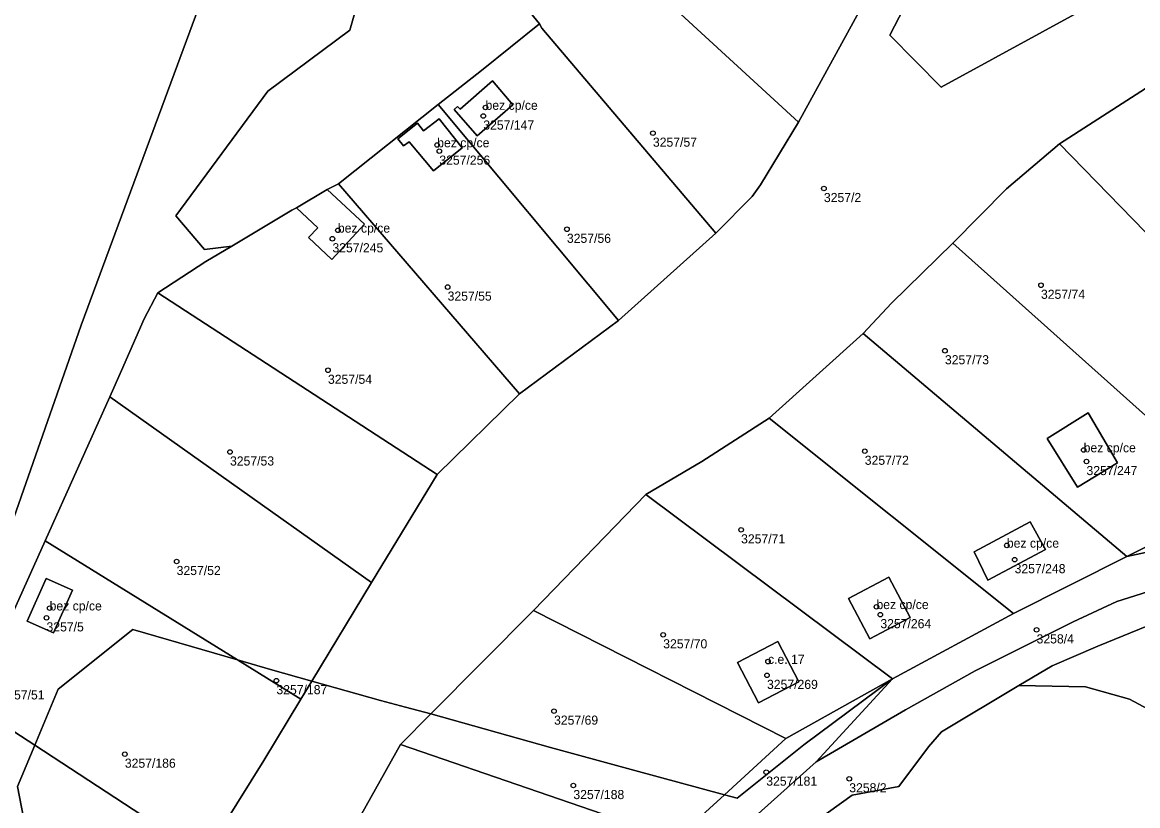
# Model space of a CAD drawing. Extents: x -878211 to -870363, y -1058464 to -1052522.
# Drawn here: x -876063.3 to -875941, y -1056644.4 to -1056558.5 of the extents above; entities that cross this region are included whole.
import ezdxf

# ---------------------------------------------------------------- set-up
doc = ezdxf.new("R2010")
doc.units = 0
for name, color, linetype in [('Definiční body', 7, 'Continuous'), ('Polygon budovy', 7, 'Continuous'), ('Polygon parcely', 7, 'Continuous')]:
    doc.layers.add(name, color=color, linetype=linetype)

msp = doc.modelspace()

# ---------------------------------------------------------------- linework, layer by layer
at = {"layer": 'Definiční body'}
for centre in [(-876012.71, -1056568.79994), (-876012.46, -1056567.86994), (-875994.11, -1056570.67994), (-876017.76, -1056571.97994), (-876017.53, -1056572.64994), (-875975.36, -1056576.74994), (-876003.54, -1056581.21994), (-876029.25, -1056582.25994), (-876028.65, -1056581.33994), (-875951.56, -1056587.35994), (-876016.62, -1056587.55994), (-875962.09, -1056594.53994), (-876029.74, -1056596.67994), (-876040.48, -1056605.63994), (-875970.88, -1056605.55994), (-875946.88, -1056605.42994), (-875946.57, -1056606.68994), (-875984.44, -1056614.17994), (-875955.3, -1056615.88994), (-876046.33, -1056617.64994), (-875954.45, -1056617.44994), (-876060.26, -1056622.76994), (-875969.6, -1056622.61994), (-876060.6, -1056623.82994), (-875969.17, -1056623.47994), (-875952.04, -1056625.14994), (-875992.98, -1056625.68994), (-875981.49, -1056628.62994), (-875981.6, -1056630.13994), (-876035.39, -1056630.71994), (-876004.95, -1056634.05994), (-876052.01, -1056638.77994), (-875981.68, -1056640.74994), (-876002.83, -1056642.21994), (-875972.58, -1056641.47994)]:
    msp.add_circle(centre, 0.25, dxfattribs=at)
at = {"layer": 'Polygon budovy'}
for points in [[(-876015.52, -1056567.76), (-876015.9, -1056568.09), (-876013.38, -1056570.98), (-876009.47, -1056567.58), (-876011.69, -1056564.96), (-876015.26, -1056568.06)], [(-876022.07, -1056571.29), (-876021.45, -1056572.06), (-876020.84, -1056571.63), (-876018.17, -1056574.83), (-876015.03, -1056572.28), (-876017.54, -1056569.11), (-876019.27, -1056570.43), (-876019.93, -1056569.59)], [(-876033.2, -1056578.86), (-876030.85, -1056581.06), (-876031.87, -1056582.14), (-876029.33, -1056584.52), (-876025.75, -1056580.65), (-876028.29, -1056578.3), (-876029.84, -1056576.87)], [(-875946.39, -1056601.36), (-875950.88, -1056604.15), (-875947.56, -1056609.49), (-875943.18, -1056606.83)], [(-875952.75, -1056613.31), (-875958.9, -1056616.58), (-875957.37, -1056619.69), (-875951.05, -1056616.32)], [(-876060.64, -1056619.51), (-876062.72, -1056624.18), (-876059.83, -1056625.47), (-876057.75, -1056620.8)], [(-875970.34, -1056626.14), (-875965.91, -1056623.8), (-875968.23, -1056619.37), (-875972.67, -1056621.7)], [(-875980.42, -1056626.43), (-875984.84, -1056628.74), (-875982.53, -1056633.16), (-875978.12, -1056630.85)]]:
    msp.add_lwpolyline(points, close=True, dxfattribs=at)
at = {"layer": 'Polygon parcely'}
for points in [[(-876148.16, -1056700.5), (-876121.62, -1056691.73), (-876103.64, -1056686.72), (-876104.28, -1056684.6), (-876085.87, -1056679.29), (-876080.06, -1056675.29), (-876078.71, -1056672.13), (-876081.31, -1056671.52), (-876075.34, -1056648.03), (-876070.94, -1056638.08), (-876069.67, -1056630.78), (-876064.71, -1056614.32), (-876056.8, -1056591.72), (-876042.56, -1056553.18), (-876035.37, -1056538.13), (-876027.85, -1056524.56), (-876017.07, -1056511.44), (-876044.68, -1056501.38), (-876098.73, -1056474.1), (-876103.25, -1056477.52), (-876108.02, -1056486.39), (-876113.38, -1056501.74), (-876122.52, -1056533.99), (-876125.96, -1056540.6)], [(-875929.59, -1056547.61), (-875962.51, -1056565.65), (-875968.14, -1056559.94), (-875953.65, -1056531.96), (-875951.53, -1056527.78), (-875942.56, -1056510.03), (-875938.39, -1056502.15)], [(-876042.56, -1056553.18), (-876056.8, -1056591.72), (-876064.71, -1056614.32), (-876069.67, -1056630.78), (-876070.94, -1056638.08), (-876068.81, -1056633.28), (-876060.76, -1056615.37), (-876053.64, -1056599.58), (-876052.39, -1056596.71), (-876049.88, -1056591.06), (-876048.41, -1056588.2), (-876043.14, -1056584.76), (-876040.29, -1056583.07), (-876043.26, -1056583.45), (-876046.42, -1056579.75), (-876036.33, -1056566.09), (-876027.33, -1056559.37), (-876025.32, -1056552.32)], [(-875970.92, -1056556.29), (-875978.16, -1056569.49), (-875982.3, -1056576.34), (-875983.24, -1056577.61), (-875987.21, -1056581.66), (-875997.87, -1056591.22), (-876008.73, -1056599.26), (-876017.77, -1056608.11), (-876024.97, -1056619.97), (-876031.52, -1056630.78), (-876023.99, -1056632.88), (-876021.23, -1056633.64), (-876018.46, -1056634.36), (-876007.19, -1056623.03), (-875994.9, -1056610.31), (-875988.74, -1056606.68), (-875981.38, -1056601.92), (-875971.05, -1056592.66), (-875967.95, -1056589.32), (-875961.23, -1056582.75), (-875955.33, -1056576.78), (-875949.52, -1056571.85), (-875937.43, -1056564.05)], [(-875935.73, -1056619.65), (-875943.26, -1056622.04), (-875948.03, -1056624.28), (-875958.78, -1056629.66), (-875966.41, -1056633.91), (-875976.21, -1056639.64), (-875988.19, -1056650.37)], [(-875981.23, -1056649.71), (-875972.28, -1056643.28), (-875967.15, -1056642.32), (-875963.88, -1056637.97), (-875962.48, -1056636.34), (-875953.97, -1056631.25), (-875950.35, -1056629.09), (-875945.33, -1056626.95), (-875933.59, -1056622.15)], [(-875933.59, -1056622.15), (-875945.33, -1056626.95), (-875950.35, -1056629.09), (-875953.97, -1056631.25), (-875946.69, -1056631.41), (-875941.86, -1056632.75), (-875938.32, -1056634.64)], [(-876027.79, -1056648.44), (-876021.8, -1056637.72), (-876018.46, -1056634.36), (-876021.23, -1056633.64), (-876023.99, -1056632.88), (-876031.52, -1056630.78), (-876032.72, -1056632.76), (-876036.77, -1056639.49), (-876041.11, -1056646.44)], [(-875988.19, -1056650.37), (-875976.21, -1056639.64), (-875967.84, -1056630.53), (-875977.58, -1056637.75), (-875984.86, -1056643.61), (-875986.26, -1056643.23), (-875991.6, -1056648.12)]]:
    msp.add_lwpolyline(points, dxfattribs=at)
for points in [[(-876033.7, -1056579.14), (-876033.2, -1056578.86), (-876029.84, -1056576.87), (-876028.59, -1056576.22), (-876017.66, -1056567.53), (-876012.91, -1056563.82), (-876006.55, -1056558.69), (-876008.68, -1056556.1), (-876001.27, -1056548.21), (-876001.17, -1056544.81), (-875996.5, -1056537.93), (-875993.65, -1056529.19), (-876008.08, -1056523.8), (-876009.22, -1056526.08), (-876016.63, -1056529.3), (-876027.47, -1056543.35), (-876025.32, -1056552.32), (-876027.33, -1056559.37), (-876036.33, -1056566.09), (-876046.42, -1056579.75), (-876043.26, -1056583.45), (-876040.29, -1056583.07)], [(-875926.65, -1056546.29), (-875951.53, -1056527.78), (-875953.65, -1056531.96), (-875968.14, -1056559.94), (-875962.51, -1056565.65), (-875929.59, -1056547.61)], [(-876001.17, -1056544.81), (-876001.27, -1056548.21), (-875978.16, -1056569.49), (-875970.92, -1056556.29), (-875996.5, -1056537.93)], [(-876001.27, -1056548.21), (-876008.68, -1056556.1), (-876006.55, -1056558.69), (-876006.28, -1056559.16), (-875987.21, -1056581.66), (-875983.24, -1056577.61), (-875982.3, -1056576.34), (-875978.16, -1056569.49)], [(-875987.21, -1056581.66), (-876006.28, -1056559.16), (-876006.55, -1056558.69), (-876012.91, -1056563.82), (-876017.66, -1056567.53), (-875997.87, -1056591.22)], [(-876013.38, -1056570.98), (-876015.9, -1056568.09), (-876015.52, -1056567.76), (-876015.26, -1056568.06), (-876011.69, -1056564.96), (-876009.47, -1056567.58)], [(-876013.38, -1056570.98), (-876009.47, -1056567.58), (-876011.69, -1056564.96), (-876015.26, -1056568.06), (-876015.52, -1056567.76), (-876015.9, -1056568.09)], [(-875904.3, -1056603.6), (-875937.43, -1056564.05), (-875949.52, -1056571.85), (-875915.94, -1056606.34)], [(-876028.59, -1056576.22), (-876008.73, -1056599.26), (-875997.87, -1056591.22), (-876017.66, -1056567.53)], [(-876019.93, -1056569.59), (-876019.27, -1056570.43), (-876017.54, -1056569.11), (-876015.03, -1056572.28), (-876018.17, -1056574.83), (-876020.84, -1056571.63), (-876021.45, -1056572.06), (-876022.07, -1056571.29)], [(-876019.93, -1056569.59), (-876022.07, -1056571.29), (-876021.45, -1056572.06), (-876020.84, -1056571.63), (-876018.17, -1056574.83), (-876015.03, -1056572.28), (-876017.54, -1056569.11), (-876019.27, -1056570.43)], [(-875949.52, -1056571.85), (-875955.33, -1056576.78), (-875961.23, -1056582.75), (-875929.71, -1056610.93), (-875924.9, -1056608.92), (-875915.94, -1056606.34)], [(-876029.84, -1056576.87), (-876028.29, -1056578.3), (-876025.75, -1056580.65), (-876029.33, -1056584.52), (-876031.87, -1056582.14), (-876030.85, -1056581.06), (-876033.2, -1056578.86), (-876033.7, -1056579.14), (-876040.29, -1056583.07), (-876043.14, -1056584.76), (-876048.41, -1056588.2), (-876017.77, -1056608.11), (-876008.73, -1056599.26), (-876028.59, -1056576.22)], [(-876029.84, -1056576.87), (-876033.2, -1056578.86), (-876030.85, -1056581.06), (-876031.87, -1056582.14), (-876029.33, -1056584.52), (-876025.75, -1056580.65), (-876028.29, -1056578.3)], [(-875929.71, -1056610.93), (-875961.23, -1056582.75), (-875967.95, -1056589.32), (-875971.05, -1056592.66), (-875942.16, -1056617.12)], [(-875898.91, -1056608.66), (-875888.18, -1056605.44), (-875877.78, -1056602.31), (-875869.14, -1056599.76), (-875861.65, -1056591.09), (-875872.13, -1056594.15), (-875866.23, -1056586.36), (-875867.46, -1056583.72), (-875868.42, -1056584.3), (-875879.98, -1056594.19), (-875877.36, -1056597.92), (-875890.52, -1056600.59), (-875904.3, -1056603.6), (-875915.94, -1056606.34), (-875924.9, -1056608.92), (-875929.71, -1056610.93), (-875942.16, -1056617.12), (-875924.44, -1056613.32), (-875915.9, -1056612.51), (-875910.62, -1056612.25), (-875907.63, -1056611.18)], [(-876048.41, -1056588.2), (-876049.88, -1056591.06), (-876052.39, -1056596.71), (-876053.64, -1056599.58), (-876024.97, -1056619.97), (-876017.77, -1056608.11)], [(-875942.16, -1056617.12), (-875971.05, -1056592.66), (-875981.38, -1056601.92), (-875954.59, -1056623.34)], [(-876060.76, -1056615.37), (-876039.66, -1056628.45), (-876036.04, -1056629.51), (-876031.52, -1056630.78), (-876024.97, -1056619.97), (-876053.64, -1056599.58)], [(-875943.18, -1056606.83), (-875947.56, -1056609.49), (-875950.88, -1056604.15), (-875946.39, -1056601.36)], [(-875943.18, -1056606.83), (-875946.39, -1056601.36), (-875950.88, -1056604.15), (-875947.56, -1056609.49)], [(-875994.9, -1056610.31), (-875967.84, -1056630.53), (-875954.59, -1056623.34), (-875981.38, -1056601.92), (-875988.74, -1056606.68)], [(-875994.9, -1056610.31), (-876007.19, -1056623.03), (-875979.54, -1056637.08), (-875967.84, -1056630.53)], [(-875942.16, -1056617.12), (-875954.59, -1056623.34), (-875967.84, -1056630.53), (-875976.21, -1056639.64), (-875966.41, -1056633.91), (-875958.78, -1056629.66), (-875948.03, -1056624.28), (-875943.26, -1056622.04), (-875935.73, -1056619.65), (-875925.91, -1056617.78), (-875910.62, -1056612.25), (-875915.9, -1056612.51), (-875924.44, -1056613.32)], [(-875951.05, -1056616.32), (-875957.37, -1056619.69), (-875958.9, -1056616.58), (-875952.75, -1056613.31)], [(-875951.05, -1056616.32), (-875952.75, -1056613.31), (-875958.9, -1056616.58), (-875957.37, -1056619.69)], [(-876068.81, -1056633.28), (-876061.89, -1056637.81), (-876059.31, -1056631.66), (-876051.13, -1056625.11), (-876039.66, -1056628.45), (-876060.76, -1056615.37)], [(-876059.83, -1056625.47), (-876062.72, -1056624.18), (-876060.64, -1056619.51), (-876057.75, -1056620.8)], [(-876059.83, -1056625.47), (-876057.75, -1056620.8), (-876060.64, -1056619.51), (-876062.72, -1056624.18)], [(-875970.34, -1056626.14), (-875972.67, -1056621.7), (-875968.23, -1056619.37), (-875965.91, -1056623.8)], [(-875970.34, -1056626.14), (-875965.91, -1056623.8), (-875968.23, -1056619.37), (-875972.67, -1056621.7)], [(-876007.19, -1056623.03), (-876018.46, -1056634.36), (-876005.33, -1056638.04), (-875996.11, -1056640.58), (-875986.26, -1056643.23), (-875979.54, -1056637.08)], [(-876032.72, -1056632.76), (-876039.66, -1056628.45), (-876051.13, -1056625.11), (-876059.31, -1056631.66), (-876061.89, -1056637.81), (-876043.28, -1056649.98), (-876041.11, -1056646.44), (-876036.77, -1056639.49)], [(-875980.42, -1056626.43), (-875978.12, -1056630.85), (-875982.53, -1056633.16), (-875984.84, -1056628.74)], [(-875980.42, -1056626.43), (-875984.84, -1056628.74), (-875982.53, -1056633.16), (-875978.12, -1056630.85)], [(-876031.52, -1056630.78), (-876036.04, -1056629.51), (-876039.66, -1056628.45), (-876032.72, -1056632.76)], [(-875979.54, -1056637.08), (-875986.26, -1056643.23), (-875984.86, -1056643.61), (-875977.58, -1056637.75), (-875967.84, -1056630.53)], [(-875936.43, -1056636.51), (-875938.32, -1056634.64), (-875941.86, -1056632.75), (-875946.69, -1056631.41), (-875953.97, -1056631.25), (-875962.48, -1056636.34), (-875963.88, -1056637.97), (-875967.15, -1056642.32), (-875972.28, -1056643.28), (-875981.23, -1056649.71), (-875968.32, -1056650.96), (-875958.18, -1056653.12), (-875952.73, -1056653.82), (-875948.43, -1056657.71), (-875947.92, -1056664.78), (-875935.92, -1056641.4), (-875935.69, -1056638.48)], [(-876075.34, -1056648.03), (-876060.98, -1056657.73), (-876061.1, -1056656.09), (-876063.79, -1056642.33), (-876061.89, -1056637.81), (-876068.81, -1056633.28), (-876070.94, -1056638.08)], [(-875991.6, -1056648.12), (-875986.26, -1056643.23), (-875996.11, -1056640.58), (-876005.33, -1056638.04), (-876018.46, -1056634.36), (-876021.8, -1056637.72)], [(-876043.28, -1056649.98), (-876061.89, -1056637.81), (-876063.79, -1056642.33), (-876061.1, -1056656.09), (-876060.98, -1056657.73), (-876051.83, -1056663.92)], [(-875999.3, -1056658.08), (-875991.6, -1056648.12), (-876021.8, -1056637.72), (-876027.79, -1056648.44)]]:
    msp.add_lwpolyline(points, close=True, dxfattribs=at)

# ---------------------------------------------------------------- texts
at = {"layer": 'Definiční body'}
for s, p in [('bez cp/ce', (-876012.46, -1056568.12)), ('3257/147', (-876012.71, -1056570.289)), ('bez cp/ce', (-876017.76, -1056572.23)), ('3257/57', (-875994.11, -1056572.169)), ('3257/256', (-876017.53, -1056574.139)), ('3257/2', (-875975.36, -1056578.239)), ('bez cp/ce', (-876028.65, -1056581.59)), ('3257/56', (-876003.54, -1056582.709)), ('3257/245', (-876029.25, -1056583.749)), ('3257/55', (-876016.62, -1056589.049)), ('3257/74', (-875951.56, -1056588.849)), ('3257/73', (-875962.09, -1056596.029)), ('3257/54', (-876029.74, -1056598.169)), ('bez cp/ce', (-875946.88, -1056605.679)), ('3257/53', (-876040.48, -1056607.129)), ('3257/72', (-875970.88, -1056607.049)), ('3257/247', (-875946.57, -1056608.179)), ('3257/71', (-875984.44, -1056615.669)), ('bez cp/ce', (-875955.3, -1056616.139)), ('3257/52', (-876046.33, -1056619.139)), ('3257/248', (-875954.45, -1056618.939)), ('bez cp/ce', (-876060.26, -1056623.02)), ('bez cp/ce', (-875969.6, -1056622.87)), ('3257/5', (-876060.6, -1056625.319)), ('3257/264', (-875969.17, -1056624.969)), ('3257/70', (-875992.98, -1056627.179)), ('3258/4', (-875952.04, -1056626.639)), ('c.e. 17', (-875981.49, -1056628.879)), ('3257/187', (-876035.39, -1056632.209)), ('3257/269', (-875981.6, -1056631.629)), ('3257/51', (-876065.65, -1056632.779)), ('3257/69', (-876004.95, -1056635.549)), ('3257/186', (-876052.01, -1056640.269)), ('3257/181', (-875981.68, -1056642.239)), ('3258/2', (-875972.58, -1056642.969)), ('3257/188', (-876002.83, -1056643.709))]:
    msp.add_text(s, height=0.999996, dxfattribs=at).set_placement(p)

doc.saveas('drawing.dxf')
